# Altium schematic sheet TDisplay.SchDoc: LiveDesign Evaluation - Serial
size A3; Organization: Altium Limited; Address1: L3, 12a Rodborough Rd; Address2: Frenchs Forest; Address3: NSW; Address4: Australia 2086; DocumentNumber: 3; SheetNumber: 3; SheetTotal: 7
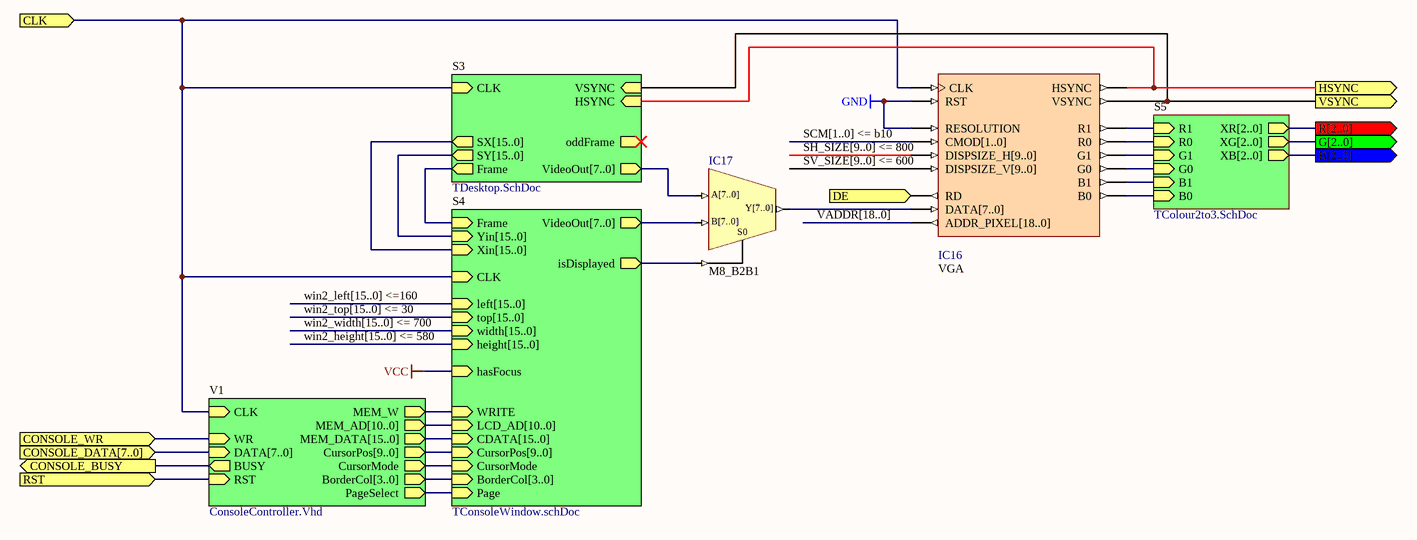
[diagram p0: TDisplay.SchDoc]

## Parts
IC16  VGA
IC17  M8_B2B1

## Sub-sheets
S3 = TDesktop.SchDoc: CLK (in), VideoOut[7..0] (out), SX[15..0] (out), SY[15..0] (out), HSYNC (in), VSYNC (in), Frame (out), oddFrame (out)
S4 = TConsoleWindow.schDoc: CLK (in), VideoOut[7..0] (out), Xin[15..0] (in), Yin[15..0] (in), top[15..0] (in), width[15..0] (in), height[15..0] (in), left[15..0] (in), isDisplayed (out), hasFocus (in), Frame (in), WRITE (in), LCD_AD[10..0] (in), CDATA[15..0] (in), CursorPos[9..0] (in), CursorMode (in), BorderCol[3..0] (in), Page (in)
S5 = TColour2to3.SchDoc: XR[2..0] (out), XG[2..0] (out), XB[2..0] (out), R1 (in), R0 (in), G1 (in), G0 (in), B1 (in), B0 (in)
V1 = ConsoleController.Vhd: WR (in), DATA[7..0] (in), BUSY (out), RST (in), MEM_W (out), MEM_AD[10..0] (out), MEM_DATA[15..0] (out), CLK (in), CursorPos[9..0] (out), CursorMode (out), BorderCol[3..0] (out), PageSelect (out)

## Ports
B[2..0] (out), CLK (in), CONSOLE_BUSY (out), CONSOLE_DATA[7..0] (in), CONSOLE_WR (in), DE (out), G[2..0] (out), HSYNC (out), R[2..0] (out), RST (in), VSYNC (out)

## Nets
GND: IC16.RESOLUTION IC16.RST
CLK: IC16.CLK ; port CLK, sheet S3/CLK, sheet S4/CLK, sheet V1/CLK
CONSOLE_BUSY: port CONSOLE_BUSY, sheet V1/BUSY
CONSOLE_WR: port CONSOLE_WR, sheet V1/WR
DE: IC16.RD ; port DE
HSYNC: IC16.HSYNC ; port HSYNC, sheet S3/HSYNC
RST: port RST, sheet V1/RST
VSYNC: IC16.VSYNC ; port VSYNC, sheet S3/VSYNC
NetIC16_B0: IC16.B0 ; sheet S5/B0
NetIC16_B1: IC16.B1 ; sheet S5/B1
NetIC16_G0: IC16.G0 ; sheet S5/G0
NetIC16_G1: IC16.G1 ; sheet S5/G1
NetIC16_R0: IC16.R0 ; sheet S5/R0
NetIC16_R1: IC16.R1 ; sheet S5/R1
NetIC17_S0: IC17.S0 ; sheet S4/isDisplayed
(unnamed): sheet S3/Frame, sheet S4/Frame
(unnamed): sheet S4/WRITE, sheet V1/MEM_W  [a separate net that carries the same name]
(unnamed): sheet S4/CursorMode, sheet V1/CursorMode  [a separate net that carries the same name]
(unnamed): sheet S4/Page, sheet V1/PageSelect  [a separate net that carries the same name]

Not connected (* = marked no-connect by the designer): IC16 ADDR_PIXEL[18..0] CMOD[1..0] DATA[7..0] DISPSIZE_H[9..0] DISPSIZE_V[9..0]; IC17 A[7..0] B[7..0] Y[7..0]

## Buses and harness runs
bus port B[2..0] = sheet S5/XB[2..0]
bus port CONSOLE_DATA[7..0] = sheet V1/DATA[7..0]
bus port G[2..0] = sheet S5/XG[2..0]
bus port R[2..0] = sheet S5/XR[2..0]
bus SCM[1..0] <= b10
bus SH_SIZE[9..0] <= 800
bus sheet S3/SX[15..0] = sheet S4/Xin[15..0]
bus sheet S3/SY[15..0] = sheet S4/Yin[15..0]
bus sheet S4/BorderCol[3..0] = sheet V1/BorderCol[3..0]
bus sheet S4/CDATA[15..0] = sheet V1/MEM_DATA[15..0]
bus sheet S4/CursorPos[9..0] = sheet V1/CursorPos[9..0]
bus sheet S4/LCD_AD[10..0] = sheet V1/MEM_AD[10..0]
bus SV_SIZE[9..0] <= 600
bus VADDR[18..0]
bus win2_height[15..0] <= 580 = sheet S4/height[15..0]
bus win2_left[15..0] <=160 = sheet S4/left[15..0]
bus win2_top[15..0] <= 30 = sheet S4/top[15..0]
bus win2_width[15..0] <= 700 = sheet S4/width[15..0]

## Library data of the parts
IC16 = VGA: VGA Controller
IC17 = M8_B2B1: 2x8-Bit Bus to 1x8-Bit Bus Multiplexer; ArchiveName: GENERIC; VHDLIB_SIM: GENERIC_LIB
